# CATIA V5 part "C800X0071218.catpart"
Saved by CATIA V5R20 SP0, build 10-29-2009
Part number: C800X0071218
Source: Unknown
Property "A": "30"
Property "ARTICLENO": "C800X0071218"
Property "B": "13"
Property "BOMINFO": "C800X0071218"
Property "C": "46"
Property "CA": "C800X0071218"
Property "D1": "38"
Property "DES": "ROTATING EYEBOLT WITH RING Ton 0,7 M12x18"
Property "E": "50"
Property "H": "105"
Property "L": "18"
Property "LINA": "C800X0071218"
Property "NB": "C800X0071218"
Property "NBSYN": "$CODE."
Property "NN": "C800X"
Property "NT": "Rotating eyebolt with ring"
Property "SIZE": "M12"
Property "SUPPLIER": "CF"
Property "SW": "30"
Property "WEIGHT": "500"
Property "WLL": "0.70"
Bounding box of the stored display mesh (mm): x -27.837 to 27.837, y -18 to 117.837, z -19 to 19
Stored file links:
  C:\Users\Utente\Desktop\3D files 800X\C800X0071218.catpart
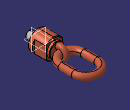
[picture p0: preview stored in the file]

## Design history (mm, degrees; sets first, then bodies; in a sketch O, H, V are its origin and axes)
Body1 "Geometry.1" (main body)
  Solid1 "C800X0071218.catpart": solid without history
